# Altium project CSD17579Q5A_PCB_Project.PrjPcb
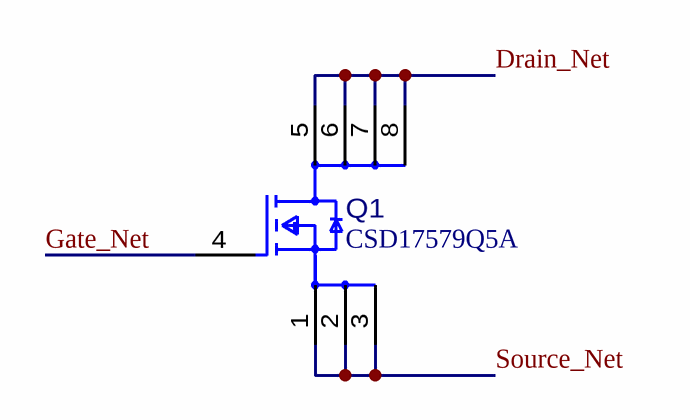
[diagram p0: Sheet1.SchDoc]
1 sheet, 1 parts. Net scope: global (net labels, ports and power ports of the same name join across sheets).
Board file: PCB1.PcbDoc

## Sheet Sheet1.SchDoc
size A4; PageSetup: Record=PageOptions¦CenterHorizontal=True¦CenterVertical=True¦PrintScale=0.93¦XCorrection=1.00¦YCorrection=1.00¦PrintKind=0¦BorderSize=5000000¦LeftOffset=0¦BottomOffset=0¦Orientation=2¦PaperLength=1000¦PaperWidth=1000¦Scale=100¦PaperSource=15¦PrintQuality=600¦MediaType=1¦DitherType=10¦PaperKind=Letter¦PrintScaleMode=1

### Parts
Q1  CSD17579Q5A  [DQJ0008A-MFG]

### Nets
Drain_Net: Q1.5(D) Q1.6(D) Q1.7(D) Q1.8(D)
Gate_Net: Q1.4(G)
Source_Net: Q1.1(S) Q1.2(S) Q1.3(S)

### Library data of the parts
Q1 = CMP-0128130-1: Trans MOSFET N-CH Si 30V 25A 8-Pin VSONP EP T/R; Manufacturer: Texas Instruments; AEC Qualified: No; QgTyp_nC: 11.6nC @ 10V; Rdson45_ohm: 8.4m; SizeZ_mm: 1.1mm; VdsMax_V: 1V; Vgs_V: 20V; Input Capacitance At Vds: 796pF @ 15V; Number Of Channels: 1; Power_W: 3.1W; Pulse Drain Current: 105A; Reverse Recovery Charge: 4.2nC; Reverse Recovery Time: 5.7ns; Rthja Max: 50°C/W; Standoff Height: 0mm; Threshold Vgs Max: 2V; TJmax_C: +150°C; Transconductance: 36S; Turn Off Delay Time: 13ns; Turn On Delay Time: 3ns; Typ Forward Diode Voltage: 0.8V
